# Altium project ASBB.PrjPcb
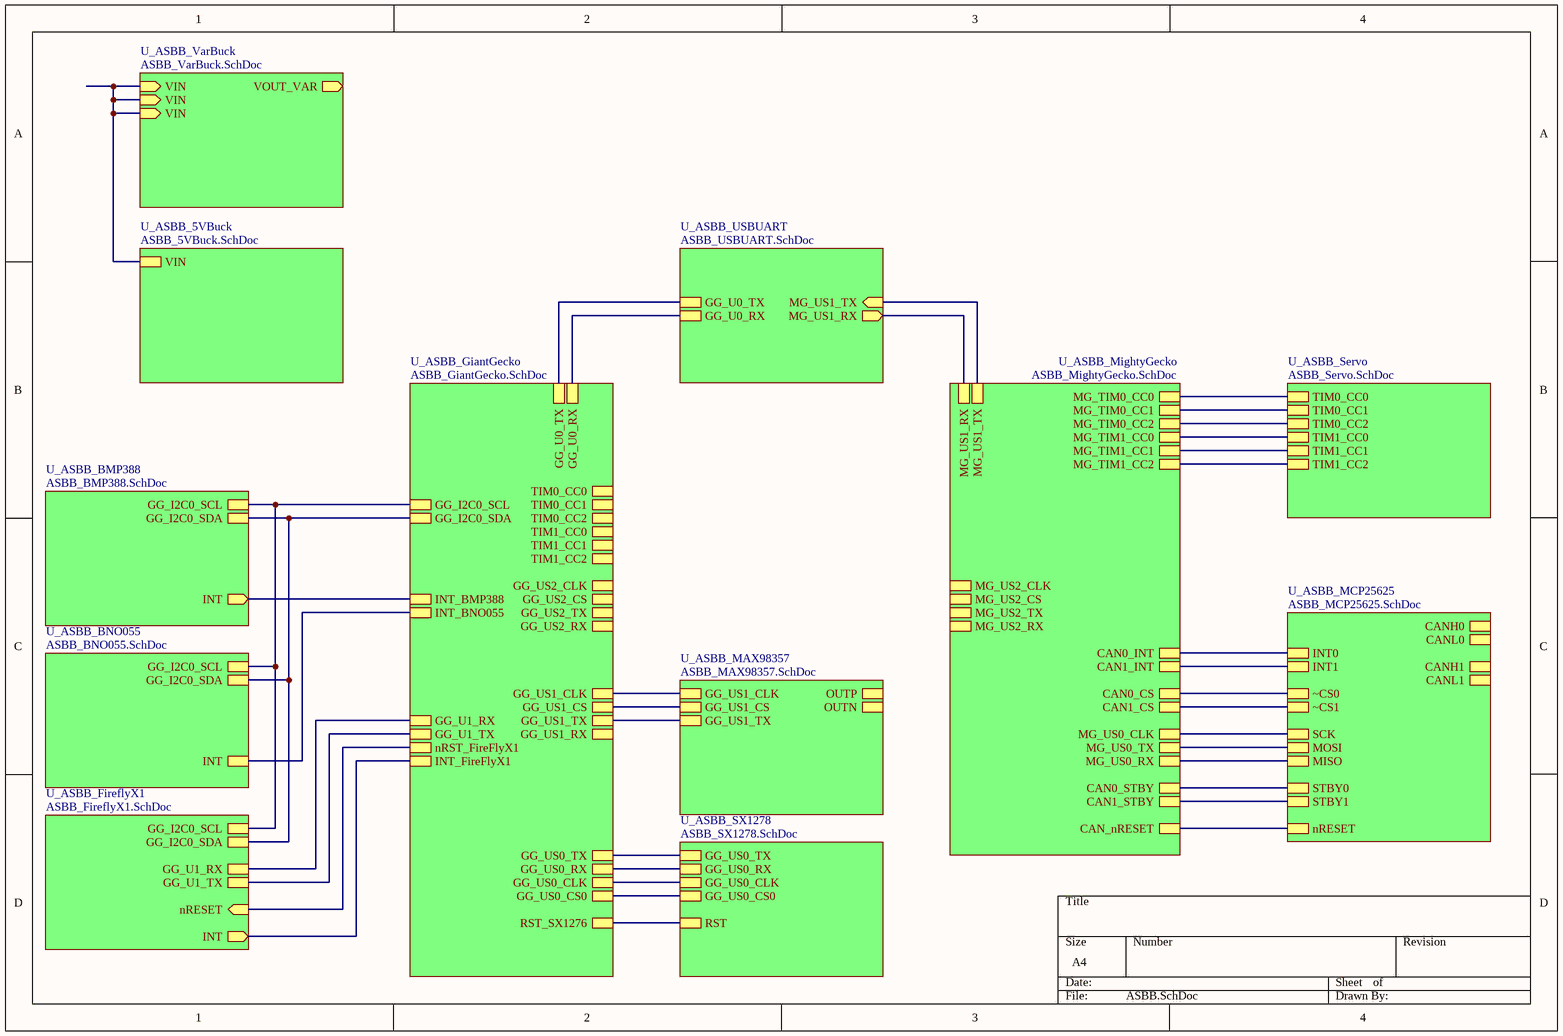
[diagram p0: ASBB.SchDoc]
13 sheets, 166 parts. Net scope: hierarchical (ports join the sheet entries above them; power ports are global).
Sheets:
  ASBB.SchDoc
    U_ASBB_VarBuck = ASBB_VarBuck.SchDoc
    U_ASBB_5VBuck = ASBB_5VBuck.SchDoc
    U_ASBB_USBUART = ASBB_USBUART.SchDoc
    U_ASBB_BMP388 = ASBB_BMP388.SchDoc
    U_ASBB_BNO055 = ASBB_BNO055.SchDoc
    U_ASBB_MAX98357 = ASBB_MAX98357.SchDoc
    U_ASBB_MCP25625 = ASBB_MCP25625.SchDoc
    U_ASBB_FireflyX1 = ASBB_FireflyX1.SchDoc
    U_ASBB_SX1278 = ASBB_SX1278.SchDoc
    U_ASBB_GiantGecko = ASBB_GiantGecko.SchDoc
    U_ASBB_Servo = ASBB_Servo.SchDoc
    U_ASBB_MightyGecko = ASBB_MightyGecko.SchDoc

## Sheet ASBB.SchDoc
size A4

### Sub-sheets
U_ASBB_5VBuck = ASBB_5VBuck.SchDoc: VIN
U_ASBB_BMP388 = ASBB_BMP388.SchDoc: INT (out), GG_I2C0_SCL, GG_I2C0_SDA
U_ASBB_BNO055 = ASBB_BNO055.SchDoc: INT, GG_I2C0_SCL, GG_I2C0_SDA
U_ASBB_FireflyX1 = ASBB_FireflyX1.SchDoc: INT (out), nRESET (in), GG_U1_TX, GG_I2C0_SCL, GG_U1_RX, GG_I2C0_SDA
U_ASBB_GiantGecko = ASBB_GiantGecko.SchDoc: GG_U0_TX, GG_US1_CLK, GG_US0_CS0, GG_US2_RX, GG_U1_RX, GG_US2_CLK, GG_US1_TX, GG_US0_TX, GG_US2_TX, GG_US1_RX, GG_I2C0_SDA, GG_U1_TX, GG_US2_CS, GG_U0_RX, GG_US0_RX, GG_US1_CS, GG_US0_CLK, GG_I2C0_SCL, INT_BNO055, INT_BMP388, nRST_FireFlyX1, INT_FireFlyX1, RST_SX1276, TIM1_CC1, TIM0_CC0, TIM1_CC0, TIM0_CC2, TIM1_CC2, TIM0_CC1
U_ASBB_MAX98357 = ASBB_MAX98357.SchDoc: OUTP, OUTN, GG_US1_CLK, GG_US1_CS, GG_US1_TX
U_ASBB_MCP25625 = ASBB_MCP25625.SchDoc: INT0, INT1, CANH0, CANL0, CANH1, CANL1, ~CS0, SCK, MOSI, MISO, ~CS1, STBY1, STBY0, nRESET
U_ASBB_MightyGecko = ASBB_MightyGecko.SchDoc: MG_US0_CLK, MG_US0_RX, MG_US0_TX, MG_US2_CLK, MG_US2_RX, MG_US2_TX, MG_US2_CS, MG_US1_RX, MG_US1_TX, MG_TIM0_CC0, MG_TIM1_CC0, MG_TIM0_CC1, MG_TIM0_CC2, CAN1_INT, CAN0_STBY, CAN0_CS, CAN_nRESET, CAN1_CS, CAN0_INT, CAN1_STBY, MG_TIM1_CC1, MG_TIM1_CC2
U_ASBB_Servo = ASBB_Servo.SchDoc: TIM0_CC0, TIM0_CC1, TIM0_CC2, TIM1_CC0, TIM1_CC1, TIM1_CC2
U_ASBB_SX1278 = ASBB_SX1278.SchDoc: RST, GG_US0_TX, GG_US0_RX, GG_US0_CLK, GG_US0_CS0
U_ASBB_USBUART = ASBB_USBUART.SchDoc: GG_U0_TX, GG_U0_RX, MG_US1_TX (in), MG_US1_RX (out)
U_ASBB_VarBuck = ASBB_VarBuck.SchDoc: VIN (in), VIN (in), VIN (in), VOUT_VAR (out)

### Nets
GG_US0_CLK: sheet U_ASBB_SX1278/GG_US0_CLK, sheet U_ASBB_GiantGecko/GG_US0_CLK
GG_US0_RX: sheet U_ASBB_SX1278/GG_US0_RX, sheet U_ASBB_GiantGecko/GG_US0_RX
GG_US0_TX: sheet U_ASBB_SX1278/GG_US0_TX, sheet U_ASBB_GiantGecko/GG_US0_TX
V_IN: sheet U_ASBB_VarBuck/VIN, sheet U_ASBB_VarBuck/VIN, sheet U_ASBB_VarBuck/VIN, sheet U_ASBB_5VBuck/VIN
NetB?_10: sheet U_ASBB_BMP388/GG_I2C0_SDA, sheet U_ASBB_BNO055/GG_I2C0_SDA, sheet U_ASBB_FireflyX1/GG_I2C0_SDA, sheet U_ASBB_GiantGecko/GG_I2C0_SDA
NetB?_11: sheet U_ASBB_BMP388/GG_I2C0_SCL, sheet U_ASBB_BNO055/GG_I2C0_SCL, sheet U_ASBB_FireflyX1/GG_I2C0_SCL, sheet U_ASBB_GiantGecko/GG_I2C0_SCL
NetB?_13: sheet U_ASBB_FireflyX1/INT, sheet U_ASBB_GiantGecko/INT_FireFlyX1
NetB?_19: sheet U_ASBB_FireflyX1/nRESET, sheet U_ASBB_GiantGecko/nRST_FireFlyX1
NetIC?#3_2: sheet U_ASBB_SX1278/GG_US0_CS0, sheet U_ASBB_GiantGecko/GG_US0_CS0
NetIC?#3_4: sheet U_ASBB_SX1278/RST, sheet U_ASBB_GiantGecko/RST_SX1276
NetIC?#4_4: sheet U_ASBB_MCP25625/STBY1, sheet U_ASBB_MightyGecko/CAN1_STBY
NetIC?#4_19: sheet U_ASBB_MCP25625/MOSI, sheet U_ASBB_MightyGecko/MG_US0_TX
NetIC?#4_20: sheet U_ASBB_MCP25625/MISO, sheet U_ASBB_MightyGecko/MG_US0_RX
NetIC?#4_21: sheet U_ASBB_MCP25625/SCK, sheet U_ASBB_MightyGecko/MG_US0_CLK
NetIC?#4_30: sheet U_ASBB_Servo/TIM1_CC2, sheet U_ASBB_MightyGecko/MG_TIM1_CC2
NetIC?#4_31: sheet U_ASBB_Servo/TIM1_CC1, sheet U_ASBB_MightyGecko/MG_TIM1_CC1
NetIC?#4_32: sheet U_ASBB_MCP25625/nRESET, sheet U_ASBB_MightyGecko/CAN_nRESET
NetIC?#4_33: sheet U_ASBB_USBUART/MG_US1_RX, sheet U_ASBB_MightyGecko/MG_US1_RX
NetIC?#4_34: sheet U_ASBB_USBUART/MG_US1_TX, sheet U_ASBB_MightyGecko/MG_US1_TX
NetIC?#4_45: sheet U_ASBB_Servo/TIM0_CC0, sheet U_ASBB_MightyGecko/MG_TIM0_CC0
NetIC?#4_47: sheet U_ASBB_Servo/TIM0_CC1, sheet U_ASBB_MightyGecko/MG_TIM0_CC1
NetIC?#4_49: sheet U_ASBB_Servo/TIM0_CC2, sheet U_ASBB_MightyGecko/MG_TIM0_CC2
NetIC?#4_50: sheet U_ASBB_MCP25625/STBY0, sheet U_ASBB_MightyGecko/CAN0_STBY
NetIC?#4_51: sheet U_ASBB_Servo/TIM1_CC0, sheet U_ASBB_MightyGecko/MG_TIM1_CC0
NetIC?#4_52: sheet U_ASBB_MCP25625/INT0, sheet U_ASBB_MightyGecko/CAN0_INT
NetIC?#4_54: sheet U_ASBB_MCP25625/INT1, sheet U_ASBB_MightyGecko/CAN1_INT
NetIC?#4_57: sheet U_ASBB_MCP25625/~CS0, sheet U_ASBB_MightyGecko/CAN0_CS
NetIC?#4_58: sheet U_ASBB_MCP25625/~CS1, sheet U_ASBB_MightyGecko/CAN1_CS
NetR?#28_2: sheet U_ASBB_FireflyX1/GG_U1_TX, sheet U_ASBB_GiantGecko/GG_U1_TX
NetR?#29_2: sheet U_ASBB_FireflyX1/GG_U1_RX, sheet U_ASBB_GiantGecko/GG_U1_RX
NetU?#2_2: sheet U_ASBB_USBUART/GG_U0_TX, sheet U_ASBB_GiantGecko/GG_U0_TX
NetU?#2_30: sheet U_ASBB_USBUART/GG_U0_RX, sheet U_ASBB_GiantGecko/GG_U0_RX
NetU?#3_7: sheet U_ASBB_BMP388/INT, sheet U_ASBB_GiantGecko/INT_BMP388
NetU?#4_14: sheet U_ASBB_BNO055/INT, sheet U_ASBB_GiantGecko/INT_BNO055
NetU?#5_1: sheet U_ASBB_MAX98357/GG_US1_TX, sheet U_ASBB_GiantGecko/GG_US1_TX
NetU?#5_14: sheet U_ASBB_MAX98357/GG_US1_CS, sheet U_ASBB_GiantGecko/GG_US1_CS
NetU?#5_16: sheet U_ASBB_MAX98357/GG_US1_CLK, sheet U_ASBB_GiantGecko/GG_US1_CLK

## Sheet ASBB_VarBuck.SchDoc
size A4
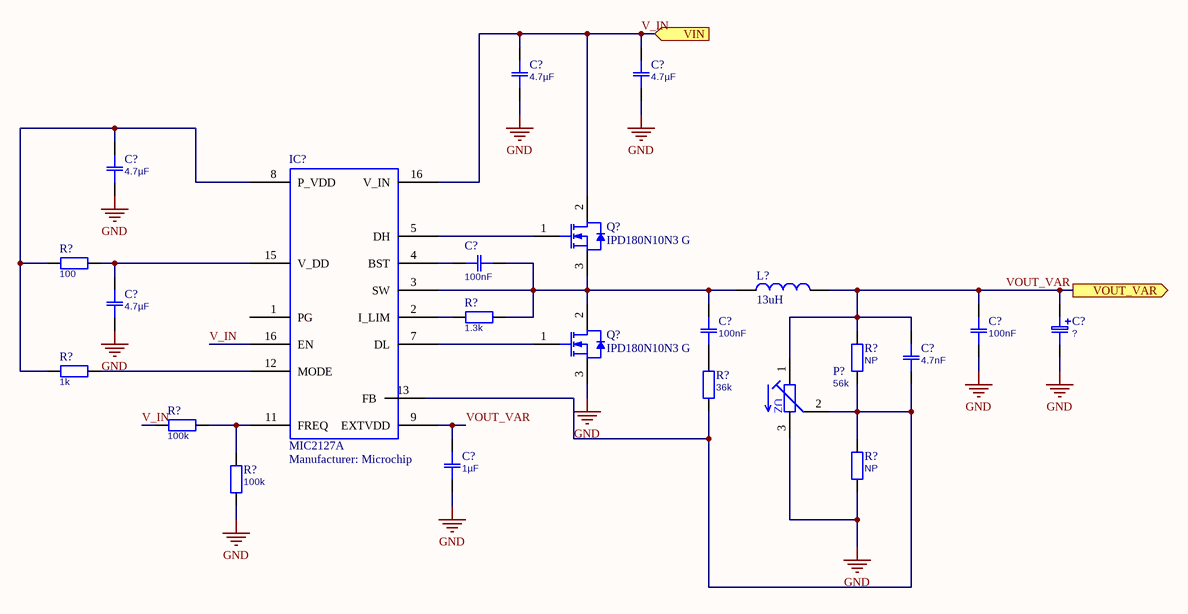
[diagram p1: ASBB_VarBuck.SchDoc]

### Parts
(Parts that share a designator on the sheet are numbered #1, #2 ... from top to bottom, then left to right.)
C?#1  4.7µF  [0603]
C?#2  4.7µF  [0603]
C?#3  4.7µF  [0603]
C?#4  100nF  [0603]
C?#5  4.7µF  [0603]
C?#6  100nF  [0603]
C?#7  100nF  [0603]
C?#8  ?  [SMELK-A]
C?#9  4.7nF  [0603]
C?#10  1µF  [0603]
IC?#1  MIC2127A  Manufacturer: Microchip  [QFN-MG16_M]
L?#1  value 13uH  [WE-HCI_1365_WE-PERM]  (hidden comment: 7443551131)
P?#1  56k  [Model 43 Trimmer]
Q?#1  IPD180N10N3 G  [INF-PG-TO252-3-11_A_N]
Q?#2  IPD180N10N3 G  [INF-PG-TO252-3-11_A_N]
R?#1  100  [0603]
R?#2  1.3k  [0603]
R?#3  1k  [0603]
R?#4  NP  [0603]
R?#5  36k  [0603]
R?#6  100k  [0603]
R?#7  NP  [0603]
R?#8  100k  [0603]

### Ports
VIN (in), VOUT_VAR (out)

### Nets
GND: C?#1.1 C?#2.1 C?#3.2 C?#5.2 C?#7.2 C?#8.2(-) C?#10.2 P?#1.3 Q?#2.3(SOURCE) R?#7.1 R?#8.1
V_IN: C?#1.2 C?#2.2 IC?#1.16(EN) Q?#1.2(DRAIN) R?#6.1 ; port VIN
VOUT_VAR: C?#7.1 C?#8.1(+) C?#9.1 C?#10.1 IC?#1.9(EXTVDD) L?#1.2 P?#1.1 R?#4.2 ; port VOUT_VAR
NetC?#3_1: C?#3.1 IC?#1.8(P_VDD) R?#1.1 R?#3.1
NetC?#4_1: C?#4.1 C?#6.1 IC?#1.3(SW) L?#1.1 Q?#1.3(SOURCE) Q?#2.2(DRAIN) R?#2.2
NetC?#4_2: C?#4.2 IC?#1.4(BST)
NetC?#5_1: C?#5.1 IC?#1.15(V_DD) R?#1.2
NetC?#6_2: C?#6.2 R?#5.2
NetC?#9_2: C?#9.2 IC?#1.13(FB) P?#1.2 R?#4.1 R?#5.1 R?#7.2
NetIC?#1_2: IC?#1.2(I_LIM) R?#2.1
NetIC?#1_5: IC?#1.5(DH) Q?#1.1(GATE)
NetIC?#1_7: IC?#1.7(DL) Q?#2.1(GATE)
NetIC?#1_11: IC?#1.11(FREQ) R?#6.2 R?#8.2
NetIC?#1_12: IC?#1.12(MODE) R?#3.2

Not connected (* = marked no-connect by the designer): IC?#1 1(PG)

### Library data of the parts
C?#1-C?#7 C?#9 C?#10 = Capacitor
C?#8 = Capacitor polarised: Capacitor, polarised
IC?#1 = MIC2127A: 75V, Synchronous Buck Controller Featuring ADaptive On-Time Control
L?#1 = 7443551131: WE-HCI SMD Flat Wire High Current Inductor, size 1365, 10A, 13uH; Material: WE-PERM
P?#1 = Potentiometer
Q?#1 Q?#2 = IPD180N10N3 G: N-Channel OptiMOS 3 Power-Transistor, 100 V VDS, 43 A ID, -55 to 175 degC, PG-TO252-3-11, Reel, Green; Manufacturer: Infineon; Green: TRUE; ID (max): 43 A; IDpuls (max): 172 A; Polarity: N; Ptot (max): 71 W; QG: 19 nC; RDS (on) (max): 18 mOhm; Rth: 2.1 K/W; RthJA (max): 75 K/W; VDS (max): 100 V; VGS(th) (max): 3.5 V; VGS(th) (min): 2 V
R?#1-R?#8 = Resistor

## Sheet ASBB_5VBuck.SchDoc
size A4
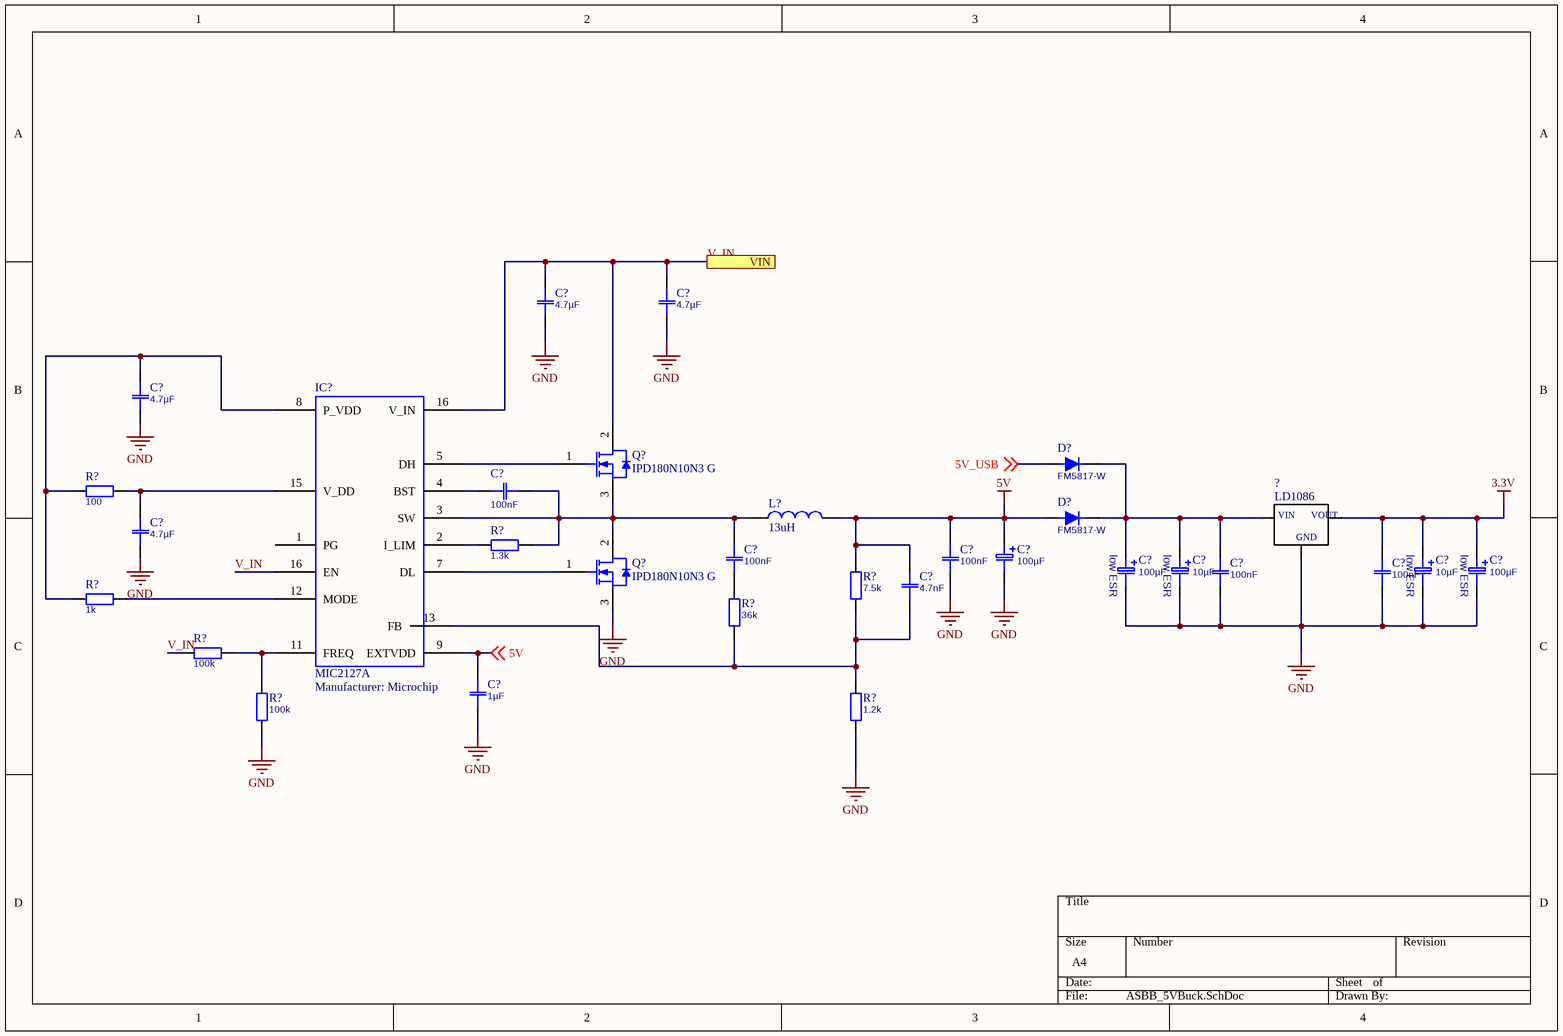
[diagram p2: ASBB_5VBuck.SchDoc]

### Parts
(Parts that share a designator on the sheet are numbered #1, #2 ... from top to bottom, then left to right.)
?  LD1086  [D2PAK_LD1086(Primary)]
C?#11  4.7µF  [0603]
C?#12  4.7µF  [0603]
C?#13  4.7µF  [0603]
C?#14  100nF  [0603]
C?#15  4.7µF  [0603]
C?#16  100nF  [0603]
C?#17  100nF  [0603]
C?#18  100µF  [SMELK-A]
C?#19  100µF  [SMELK-C]
C?#20  10µF  [SMELK-C]
C?#21  10µF  [SMELK-C]
C?#22  100µF  [SMELK-C]
C?#23  4.7nF  [0603]
C?#24  100nF  [0603]
C?#25  100nF  [0603]
C?#26  1µF  [0603]
D?#1  FM5817-W  [SMB]
D?#2  FM5817-W  [SMB]
IC?#2  MIC2127A  Manufacturer: Microchip  [QFN-MG16_M]
L?#2  value 13uH  [WE-HCI_1365_WE-PERM]  (hidden comment: 7443551131)
Q?#3  IPD180N10N3 G  [INF-PG-TO252-3-11_A_N]
Q?#4  IPD180N10N3 G  [INF-PG-TO252-3-11_A_N]
R?#9  100  [0603]
R?#10  1.3k  [0603]
R?#11  1k  [0603]
R?#12  7.5k  [0603]
R?#13  36k  [0603]
R?#14  100k  [0603]
R?#15  100k  [0603]
R?#16  1.2k  [0603]

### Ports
VIN

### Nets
3.3V: ?.VOUT C?#21.1(+) C?#22.1(+) C?#25.2
5V: C?#17.1 C?#18.1(+) C?#23.1 C?#26.1 D?#2.2(A) IC?#2.9(EXTVDD) L?#2.2 R?#12.2 ; off-sheet 5V
GND: ?.GND C?#11.1 C?#12.1 C?#13.2 C?#15.2 C?#17.2 C?#18.2(-) C?#19.2(-) C?#20.2(-) C?#21.2(-) C?#22.2(-) C?#24.1 C?#25.1 C?#26.2 Q?#4.3(SOURCE) R?#15.1 R?#16.1
5V_USB: D?#1.2(A) ; off-sheet 5V_USB
V_IN: C?#11.2 C?#12.2 IC?#2.16(EN) Q?#3.2(DRAIN) R?#14.1 ; port VIN
Net?_VIN: ?.VIN C?#19.1(+) C?#20.1(+) C?#24.2 D?#1.1(C) D?#2.1(C)
NetC?#13_1: C?#13.1 IC?#2.8(P_VDD) R?#9.1 R?#11.1
NetC?#14_1: C?#14.1 C?#16.1 IC?#2.3(SW) L?#2.1 Q?#3.3(SOURCE) Q?#4.2(DRAIN) R?#10.2
NetC?#14_2: C?#14.2 IC?#2.4(BST)
NetC?#15_1: C?#15.1 IC?#2.15(V_DD) R?#9.2
NetC?#16_2: C?#16.2 R?#13.2
NetC?#23_2: C?#23.2 IC?#2.13(FB) R?#12.1 R?#13.1 R?#16.2
NetIC?#2_2: IC?#2.2(I_LIM) R?#10.1
NetIC?#2_5: IC?#2.5(DH) Q?#3.1(GATE)
NetIC?#2_7: IC?#2.7(DL) Q?#4.1(GATE)
NetIC?#2_11: IC?#2.11(FREQ) R?#14.2 R?#15.2
NetIC?#2_12: IC?#2.12(MODE) R?#11.2

Not connected (* = marked no-connect by the designer): IC?#2 1(PG)

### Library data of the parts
? = LD1086: Semiconductors and Actives; MF: STMicroelectronics
C?#11-C?#17 C?#23-C?#26 = Capacitor
C?#18 = Capacitor polarised: Capacitor, polarised
C?#19-C?#22 = Capacitor polarised low ESR: Capacitor, polarised, low ESR
D?#1 D?#2 = Diode
IC?#2 = MIC2127A: as IC?#1 on sheet ASBB_VarBuck
L?#2 = 7443551131: as L?#1 on sheet ASBB_VarBuck
Q?#3 Q?#4 = IPD180N10N3 G: as Q?#1 on sheet ASBB_VarBuck
R?#9-R?#16 = Resistor

## Sheet ASBB_USBUART.SchDoc
size A4
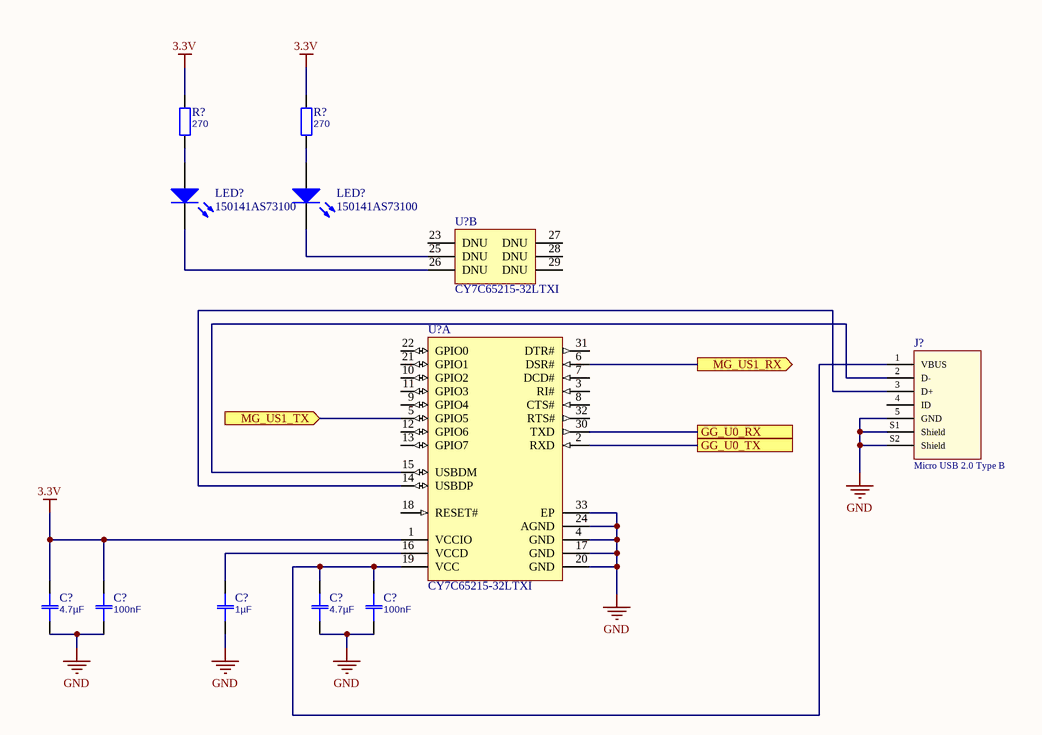
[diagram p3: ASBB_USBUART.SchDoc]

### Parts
(Parts that share a designator on the sheet are numbered #1, #2 ... from top to bottom, then left to right.)
C?#27  4.7µF  [0603]
C?#28  100nF  [0603]
C?#29  1µF  [0603]
C?#30  4.7µF  [0603]
C?#31  100nF  [0603]
J?#1  Micro USB 2.0 Type B  [614105150721]
LED?#1  150141AS73100  [3528]
LED?#2  150141AS73100  [3528]
R?#17  270  [0603]
R?#18  270  [0603]
U?#1  CY7C65215-32LTXI  [CYP-LTX32_N]  (part B of 2)
U?#2  CY7C65215-32LTXI  [CYP-LTX32_N]  (part A of 2)

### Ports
GG_U0_RX, GG_U0_TX, MG_US1_RX (out), MG_US1_TX (in)

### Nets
3.3V: C?#27.2 C?#28.2 R?#17.2 R?#18.2 U?#2.1(VCCIO)
GND: C?#27.1 C?#28.1 C?#29.1 C?#30.1 C?#31.1 J?#1.5(GND) J?#1.S1(Shield) J?#1.S2(Shield) U?#2.4(GND) U?#2.17(GND) U?#2.20(GND) U?#2.24(AGND) U?#2.33(EP)
NetC?#29_2: C?#29.2 U?#2.16(VCCD)
NetC?#30_2: C?#30.2 C?#31.2 J?#1.1(VBUS) U?#2.19(VCC)
NetIC?#4_33: U?#2.6(DSR#) ; port MG_US1_RX
NetIC?#4_34: U?#2.5(GPIO5) ; port MG_US1_TX
NetJ?#1_2: J?#1.2(D-) U?#2.15(USBDM)
NetJ?#1_3: J?#1.3(D+) U?#2.14(USBDP)
NetLED?#1_1: LED?#1.1(K) U?#1.26(DNU)
NetLED?#1_2: LED?#1.2(A) R?#17.1
NetLED?#2_1: LED?#2.1(K) U?#1.25(DNU)
NetLED?#2_2: LED?#2.2(A) R?#18.1
NetU?#2_2: U?#2.2(RXD) ; port GG_U0_TX
NetU?#2_30: U?#2.30(TXD) ; port GG_U0_RX

Not connected (* = marked no-connect by the designer): J?#1 4(ID); U?#1 23(DNU) 27(DNU) 28(DNU) 29(DNU); U?#2 3(RI#) 7(DCD#) 8(CTS#) 9(GPIO4) 10(GPIO2) 11(GPIO3) 12(GPIO6) 13(GPIO7) 18(RESET#) 21(GPIO1) 22(GPIO0) 31(DTR#) 32(RTS#)

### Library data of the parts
C?#27-C?#31 = Capacitor
J?#1 = 614105150721: Micro USB 2.0 Type B Vertical THT 5 Contacts WR-COM; Rated Current: 1 A; Gender: Female
LED?#1 LED?#2 = 150141AS73100: SMD mono-color Top LED, WL-SMTW, Amber
R?#17 R?#18 = Resistor
U?#1 U?#2 = CY7C65215-32LTXI: USB-Serial Dual Channel (UART/I2C/SPI) Bridge with CapSense(R) and BCD, 0.5 KB, 19 I/Os, 1.71 to 5.5 V, -40 to 85 degC, 32-Pin QFN (LTX32), Tray; Manufacturer: Cypress; CPU Core: M8; Max. Operating Voltage (V): 5.5; Memory Architecture: Flash; Memory Size (KB): 0.5; Min. Operating Voltage (V): 1.71; No. of I/Os: 19

## Sheet ASBB_BMP388.SchDoc
size A4
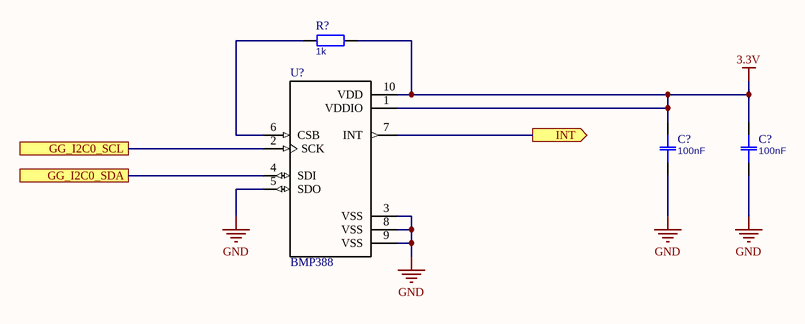
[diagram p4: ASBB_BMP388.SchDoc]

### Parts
(Parts that share a designator on the sheet are numbered #1, #2 ... from top to bottom, then left to right.)
C?#32  100nF  [0603]
C?#33  100nF  [0603]
R?#19  1k  [0603]
U?#3  BMP388  [PQFN50P200X200X80-10N]

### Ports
GG_I2C0_SCL, GG_I2C0_SDA, INT (out)

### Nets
3.3V: C?#32.2 C?#33.2 R?#19.2 U?#3.1(VDDIO) U?#3.10(VDD)
GND: C?#32.1 C?#33.1 U?#3.3(VSS) U?#3.5(SDO) U?#3.8(VSS) U?#3.9(VSS)
NetB?_10: U?#3.4(SDI) ; port GG_I2C0_SDA
NetB?_11: U?#3.2(SCK) ; port GG_I2C0_SCL
NetR?#19_1: R?#19.1 U?#3.6(CSB)
NetU?#3_7: U?#3.7(INT) ; port INT

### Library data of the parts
C?#32 C?#33 = Capacitor
R?#19 = Resistor
U?#3 = BMP388: P-Sensor SPI I2C 1, 25 Bar SMD; MF: Bosch Sensortec

## Sheet ASBB_BNO055.SchDoc
size A4
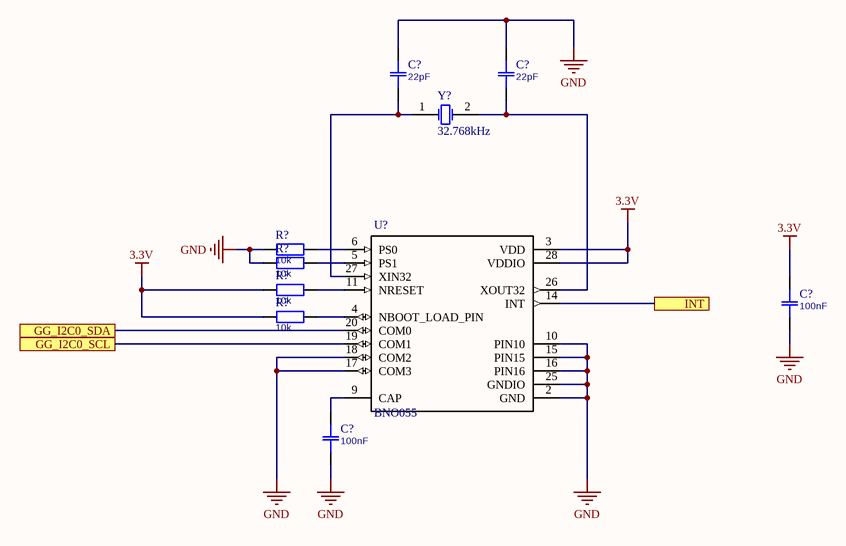
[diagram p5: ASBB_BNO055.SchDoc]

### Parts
(Parts that share a designator on the sheet are numbered #1, #2 ... from top to bottom, then left to right.)
C?#34  22pF  [0603]
C?#35  22pF  [0603]
C?#36  100nF  [0603]
C?#37  100nF  [0603]
R?#20  10k  [0603]
R?#21  10k  [0603]
R?#22  10k  [0603]
R?#23  10k  [0603]
U?#4  BNO055  [LGA28R50P4X10_380X520X100]
Y?#1  32.768kHz  [R38]

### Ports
GG_I2C0_SCL, GG_I2C0_SDA, INT

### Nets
3.3V: C?#36.2 R?#22.1 R?#23.1 U?#4.3(VDD) U?#4.28(VDDIO)
GND: C?#34.2 C?#35.2 C?#36.1 C?#37.1 R?#20.1 R?#21.1 U?#4.2(GND) U?#4.10(PIN10) U?#4.15(PIN15) U?#4.16(PIN16) U?#4.17(COM3) U?#4.18(COM2) U?#4.25(GNDIO)
NetB?_10: U?#4.20(COM0) ; port GG_I2C0_SDA
NetB?_11: U?#4.19(COM1) ; port GG_I2C0_SCL
NetC?#34_1: C?#34.1 U?#4.27(XIN32) Y?#1.1(OSC1)
NetC?#35_1: C?#35.1 U?#4.26(XOUT32) Y?#1.2(OSC2)
NetC?#37_2: C?#37.2 U?#4.9(CAP)
NetR?#20_2: R?#20.2 U?#4.6(PS0)
NetR?#21_2: R?#21.2 U?#4.5(PS1)
NetR?#22_2: R?#22.2 U?#4.11(NRESET)
NetR?#23_2: R?#23.2 U?#4.4(NBOOT_LOAD_PIN)
NetU?#4_14: U?#4.14(INT) ; port INT

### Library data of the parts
C?#34-C?#37 = Capacitor
R?#20-R?#23 = Resistor
U?#4 = BNO055: BNO055 9-axis Absolute Orientation Sensor _ SiP _ w/Sensors and Sensor Fusion; MF: Bosch
Y?#1 = XTAL: Crystal Oscillator

## Sheet ASBB_MAX98357.SchDoc
size A4
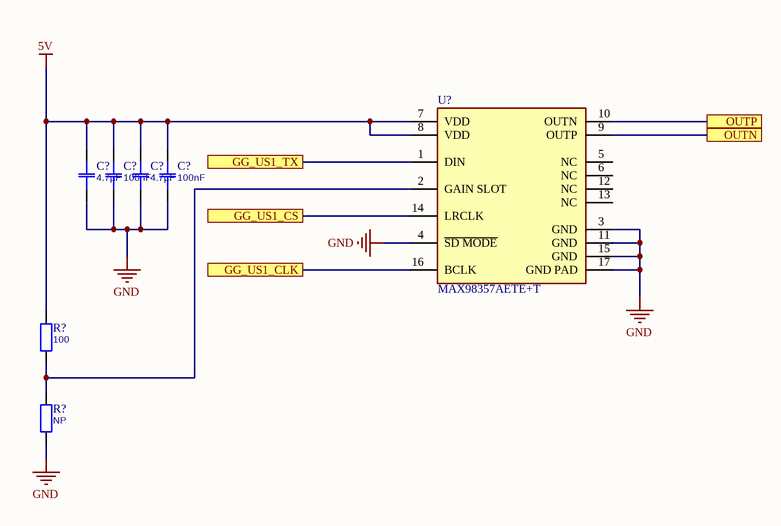
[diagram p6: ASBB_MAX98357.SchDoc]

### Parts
(Parts that share a designator on the sheet are numbered #1, #2 ... from top to bottom, then left to right.)
C?#38  4.7µF  [0603]
C?#39  100nF  [0603]
C?#40  4.7µF  [0603]
C?#41  100nF  [0603]
R?#24  100  [0603]
R?#25  NP  [0603]
U?#5  Part Number: MAX98357AETE+T  [Maxim_Electronics_21-0896_0]  (hidden comment: IC_Maxim_Electronics_MAX98357AETE+T_eec)

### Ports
GG_US1_CLK, GG_US1_CS, GG_US1_TX, OUTN, OUTP

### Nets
5V: C?#38.2 C?#39.2 C?#40.2 C?#41.2 R?#24.2 U?#5.7(VDD) U?#5.8(VDD)
GND: C?#38.1 C?#39.1 C?#40.1 C?#41.1 R?#25.1 U?#5.3(GND) U?#5.4(~{SD_MODE}) U?#5.11(GND) U?#5.15(GND) U?#5.17(GND_PAD)
NetR?#24_1: R?#24.1 R?#25.2 U?#5.2(GAIN_SLOT)
NetU?#5_1: U?#5.1(DIN) ; port GG_US1_TX
NetU?#5_9: U?#5.9(OUTP) ; port OUTN
NetU?#5_10: U?#5.10(OUTN) ; port OUTP
NetU?#5_14: U?#5.14(LRCLK) ; port GG_US1_CS
NetU?#5_16: U?#5.16(BCLK) ; port GG_US1_CLK

Not connected (* = marked no-connect by the designer): U?#5 5(NC) 6(NC) 12(NC) 13(NC)

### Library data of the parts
C?#38-C?#41 = Capacitor
R?#24 R?#25 = Resistor
U?#5 = IC_Maxim_Electronics_MAX98357AETE+T_eec: IC Amplifier IC 2-Channel (Stereo) Class D 16-TQFN (3x3); Manufacturer: Maxim Electronics; Mfg Package Ident: 21-0896

## Sheet ASBB_MCP25625.SchDoc
size A4
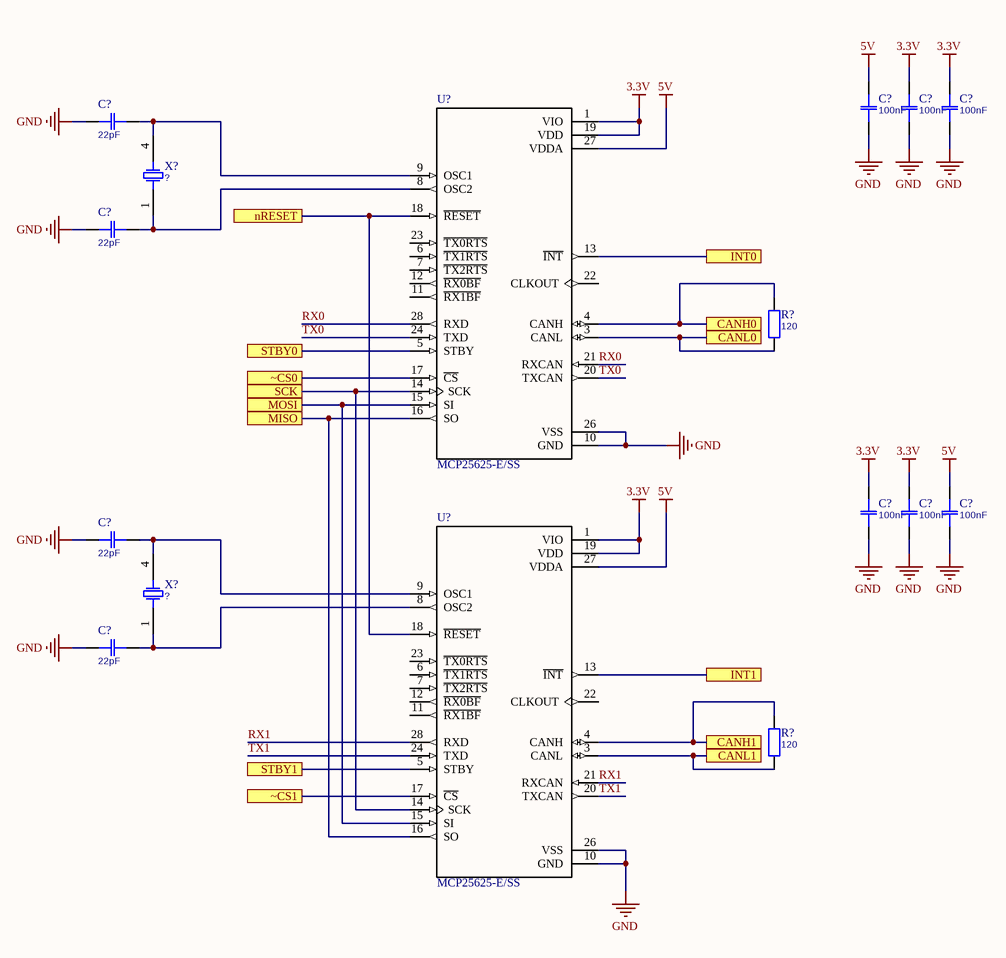
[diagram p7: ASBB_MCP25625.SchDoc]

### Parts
(Parts that share a designator on the sheet are numbered #1, #2 ... from top to bottom, then left to right.)
C?#42  100nF  [0603]
C?#43  22pF  [0603]
C?#44  100nF  [0603]
C?#45  100nF  [0603]
C?#46  22pF  [0603]
C?#47  22pF  [0603]
C?#48  100nF  [0603]
C?#49  100nF  [0603]
C?#50  100nF  [0603]
C?#51  22pF  [0603]
R?#26  120  [0603]
R?#27  120  [0603]
U?#6  MCP25625-E/SS  [SOP65P780X200-28N]
U?#7  MCP25625-E/SS  [SOP65P780X200-28N]
X?#1  ?  [MA-506]
X?#2  ?  [MA-506]

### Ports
CANH0, CANH1, CANL0, CANL1, INT0, INT1, MISO, MOSI, nRESET, SCK, STBY0, STBY1, ~CS0, ~CS1

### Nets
3.3V: C?#44.2 C?#45.2 C?#48.2 C?#49.2 U?#6.1(VIO) U?#6.19(VDD) U?#7.1(VIO) U?#7.19(VDD)
5V: C?#42.1 C?#50.2 U?#6.27(VDDA) U?#7.27(VDDA)
GND: C?#42.2 C?#43.2 C?#44.1 C?#45.1 C?#46.2 C?#47.2 C?#48.1 C?#49.1 C?#50.1 C?#51.2 U?#6.10(GND) U?#6.26(VSS) U?#7.10(GND) U?#7.26(VSS)
RX0: U?#6.21(RXCAN) U?#6.28(RXD)
RX1: U?#7.21(RXCAN) U?#7.28(RXD)
TX0: U?#6.20(TXCAN) U?#6.24(TXD)
TX1: U?#7.20(TXCAN) U?#7.24(TXD)
NetC?#43_1: C?#43.1 U?#6.9(OSC1) X?#1.4
NetC?#46_1: C?#46.1 U?#6.8(OSC2) X?#1.1
NetC?#47_1: C?#47.1 U?#7.9(OSC1) X?#2.4
NetC?#51_1: C?#51.1 U?#7.8(OSC2) X?#2.1
NetIC?#4_4: U?#7.5(STBY) ; port STBY1
NetIC?#4_19: U?#6.15(SI) U?#7.15(SI) ; port MOSI
NetIC?#4_20: U?#6.16(SO) U?#7.16(SO) ; port MISO
NetIC?#4_21: U?#6.14(SCK) U?#7.14(SCK) ; port SCK
NetIC?#4_32: U?#6.18(~{RESET}) U?#7.18(~{RESET}) ; port nRESET
NetIC?#4_50: U?#6.5(STBY) ; port STBY0
NetIC?#4_52: U?#6.13(~{INT}) ; port INT0
NetIC?#4_54: U?#7.13(~{INT}) ; port INT1
NetIC?#4_57: U?#6.17(~{CS}) ; port ~CS0
NetIC?#4_58: U?#7.17(~{CS}) ; port ~CS1
NetR?#26_1: R?#26.1 U?#6.3(CANL) ; port CANL0
NetR?#26_2: R?#26.2 U?#6.4(CANH) ; port CANH0
NetR?#27_1: R?#27.1 U?#7.3(CANL) ; port CANL1
NetR?#27_2: R?#27.2 U?#7.4(CANH) ; port CANH1

Not connected (* = marked no-connect by the designer): U?#6 6(~{TX1RTS}) 7(~{TX2RTS}) 11(~{RX1BF}) 12(~{RX0BF}) 22(CLKOUT) 23(~{TX0RTS}); U?#7 6(~{TX1RTS}) 7(~{TX2RTS}) 11(~{RX1BF}) 12(~{RX0BF}) 22(CLKOUT) 23(~{TX0RTS})

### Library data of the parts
C?#42-C?#51 = Capacitor
R?#26 R?#27 = Resistor
U?#6 U?#7 = MCP25625-E/SS: 28 SSOP .209in TUBECAN Controller with Integrated Transceiver; MF: Microchip
X?#1 X?#2 = Crystal 1-4: Crystal (Pins 1 and 4)

## Sheet ASBB_FireflyX1.SchDoc
size A4
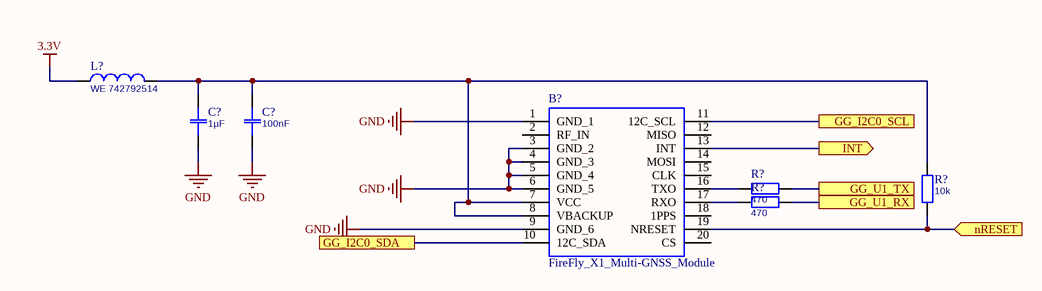
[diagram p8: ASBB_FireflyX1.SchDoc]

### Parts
(Parts that share a designator on the sheet are numbered #1, #2 ... from top to bottom, then left to right.)
B?  FireFly_X1_Multi-GNSS_Module  [X-1]
C?#52  1µF  [0603]
C?#53  100nF  [0603]
L?#3  WE 742792514  [1812]
R?#28  470  [0603]
R?#29  470  [0603]
R?#30  10k  [0603]

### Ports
GG_I2C0_SCL, GG_I2C0_SDA, GG_U1_RX, GG_U1_TX, INT (out), nRESET (in)

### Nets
3.3V: L?#3.1
GND: B?.1(GND_1) B?.3(GND_2) B?.4(GND_3) B?.5(GND_4) B?.6(GND_5) B?.9(GND_6) C?#52.1 C?#53.1
NetB?_7: B?.7(VCC) B?.8(VBACKUP) C?#52.2 C?#53.2 L?#3.2 R?#30.2
NetB?_10: B?.10(12C_SDA) ; port GG_I2C0_SDA
NetB?_11: B?.11(12C_SCL) ; port GG_I2C0_SCL
NetB?_13: B?.13(INT) ; port INT
NetB?_16: B?.16(TXO) R?#28.1
NetB?_17: B?.17(RXO) R?#29.1
NetB?_19: B?.19(NRESET) R?#30.1 ; port nRESET
NetR?#28_2: R?#28.2 ; port GG_U1_TX
NetR?#29_2: R?#29.2 ; port GG_U1_RX

Not connected (* = marked no-connect by the designer): B? 2(RF_IN) 12(MISO) 14(MOSI) 15(CLK) 18(1PPS) 20(CS)

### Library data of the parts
B? = FireFly_X1_Multi-GNSS_Module: Dual system GNSS receiver Module, QFN-20; Manufacturer_Name: GlobalTop Technology Inc.; Manufacturer_Part_Number: FireFly X1 Multi-GNSS Module
C?#52 C?#53 = Capacitor
L?#3 = Inductor
R?#28-R?#30 = Resistor

## Sheet ASBB_SX1278.SchDoc
size A4
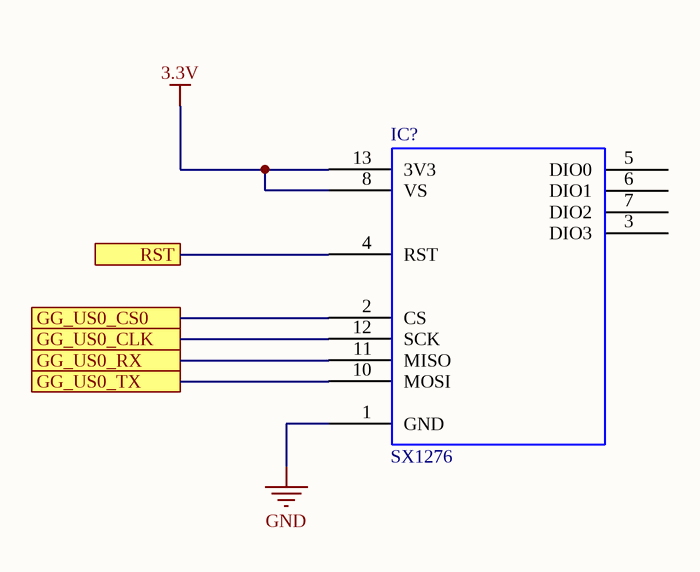
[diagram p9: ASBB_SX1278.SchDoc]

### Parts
(Parts that share a designator on the sheet are numbered #1, #2 ... from top to bottom, then left to right.)
IC?#3  SX1276  [Modtronix inAir9]

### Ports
GG_US0_CLK, GG_US0_CS0, GG_US0_RX, GG_US0_TX, RST

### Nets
3.3V: IC?#3.8(VS) IC?#3.13(3V3)
GND: IC?#3.1(GND)
GG_US0_CLK: IC?#3.12(SCK) ; port GG_US0_CLK
GG_US0_RX: IC?#3.11(MISO) ; port GG_US0_RX
GG_US0_TX: IC?#3.10(MOSI) ; port GG_US0_TX
NetIC?#3_2: IC?#3.2(CS) ; port GG_US0_CS0
NetIC?#3_4: IC?#3.4(RST) ; port RST

Not connected (* = marked no-connect by the designer): IC?#3 3(DIO3) 5(DIO0) 6(DIO1) 7(DIO2) 9(NC) 14(NC)

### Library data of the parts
IC?#3 = Modtronix inAir9: Modtronix LoRa Transceiver

## Sheet ASBB_GiantGecko.SchDoc
size A4
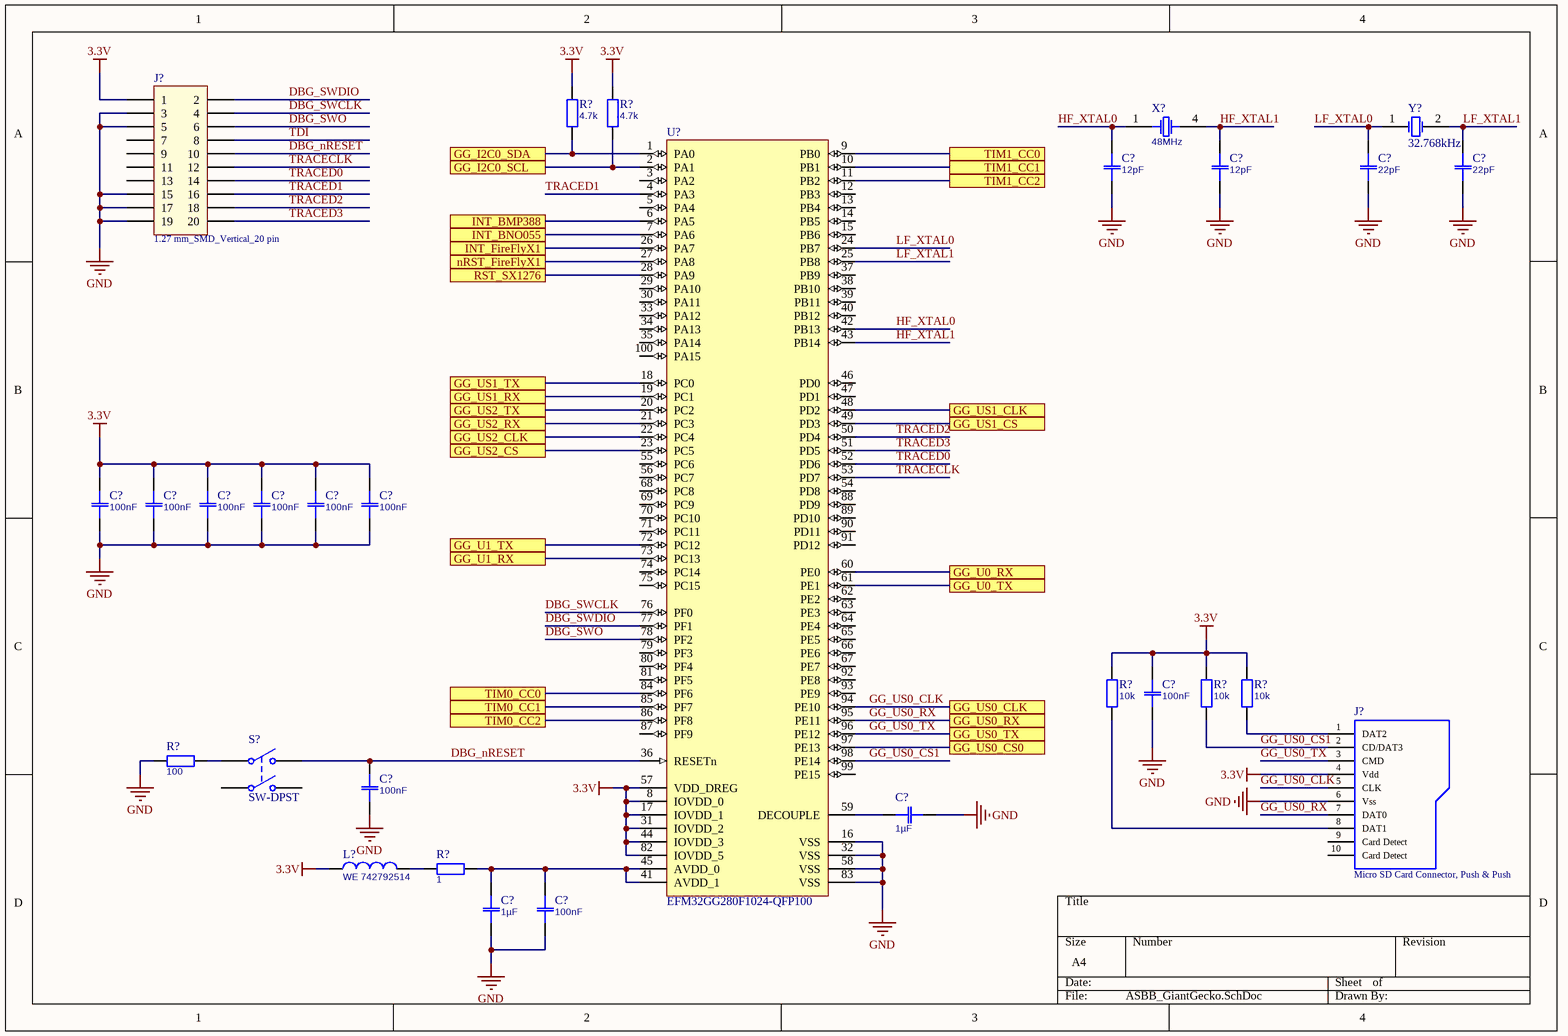
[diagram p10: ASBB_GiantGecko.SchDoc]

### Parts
(Parts that share a designator on the sheet are numbered #1, #2 ... from top to bottom, then left to right.)
C?#54  12pF  [0603]
C?#55  12pF  [0603]
C?#56  22pF  [0603]
C?#57  22pF  [0603]
C?#58  100nF  [0603]
C?#59  100nF  [0603]
C?#60  100nF  [0603]
C?#61  100nF  [0603]
C?#62  100nF  [0603]
C?#63  100nF  [0603]
C?#64  100nF  [0603]
C?#65  100nF  [0603]
C?#66  1µF  [0603]
C?#67  1µF  [0603]
C?#68  100nF  [0603]
J?#2  1.27 mm_SMD_Vertical_20 pin  [62102021021]
J?#3  Micro SD Card Connector, Push & Push  [693071010811]
L?#4  WE 742792514  [1812]
R?#31  4.7k  [0603]
R?#32  4.7k  [0603]
R?#33  10k  [0603]
R?#34  10k  [0603]
R?#35  10k  [0603]
R?#36  100  [0603]
R?#37  1  [0603]
S?  SW-DPST  [DPST-4]
U?#8  EFM32GG280F1024-QFP100  [ENMR-LQFP100_N]
X?#3  48MHz  [MA-506]
Y?#2  32.768kHz  [R38]

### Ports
GG_I2C0_SCL, GG_I2C0_SDA, GG_U0_RX, GG_U0_TX, GG_U1_RX, GG_U1_TX, GG_US0_CLK, GG_US0_CS0, GG_US0_RX, GG_US0_TX, GG_US1_CLK, GG_US1_CS, GG_US1_RX, GG_US1_TX, GG_US2_CLK, GG_US2_CS, GG_US2_RX, GG_US2_TX, INT_BMP388, INT_BNO055, INT_FireFlyX1, nRST_FireFlyX1, RST_SX1276, TIM0_CC0, TIM0_CC1, TIM0_CC2, TIM1_CC0, TIM1_CC1, TIM1_CC2

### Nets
3.3V: C?#58.1 C?#59.1 C?#60.1 C?#61.1 C?#62.1 C?#63.1 C?#64.1 J?#2.1 J?#3.4(Vdd) L?#4.1 R?#31.2 R?#32.2 R?#33.2 R?#34.2 R?#35.2 U?#8.8(IOVDD_0) U?#8.17(IOVDD_1) U?#8.31(IOVDD_2) U?#8.44(IOVDD_3) U?#8.57(VDD_DREG) U?#8.82(IOVDD_5)
GND: C?#54.2 C?#55.2 C?#56.2 C?#57.2 C?#58.2 C?#59.2 C?#60.2 C?#61.2 C?#62.2 C?#63.2 C?#64.2 C?#65.2 C?#66.2 C?#67.2 C?#68.2 J?#2.3 J?#2.5 J?#2.15 J?#2.17 J?#2.19 J?#3.6(Vss) R?#36.1 U?#8.16(VSS) U?#8.32(VSS) U?#8.58(VSS) U?#8.83(VSS)
DBG_nRESET: C?#65.1 J?#2.10 S?.2(NO1) U?#8.36(RESETn)
DBG_SWCLK: J?#2.4 U?#8.76(PF0)
DBG_SWDIO: J?#2.2 U?#8.77(PF1)
DBG_SWO: J?#2.6 U?#8.78(PF2)
GG_US0_CLK: J?#3.5(CLK) U?#8.94(PE10) ; port GG_US0_CLK
GG_US0_CS1: J?#3.2(CD/DAT3) R?#34.1 U?#8.98(PE14)
GG_US0_RX: J?#3.7(DAT0) U?#8.95(PE11) ; port GG_US0_RX
GG_US0_TX: J?#3.3(CMD) U?#8.96(PE12) ; port GG_US0_TX
HF_XTAL0: C?#54.1 U?#8.42(PB13) X?#3.1
HF_XTAL1: C?#55.1 U?#8.43(PB14) X?#3.4
LF_XTAL0: C?#56.1 U?#8.24(PB7) Y?#2.1(OSC1)
LF_XTAL1: C?#57.1 U?#8.25(PB8) Y?#2.2(OSC2)
TDI: J?#2.8
TRACECLK: J?#2.12 U?#8.53(PD7)
TRACED0: J?#2.14 U?#8.52(PD6)
TRACED1: J?#2.16 U?#8.4(PA3)
TRACED2: J?#2.18 U?#8.50(PD4)
TRACED3: J?#2.20 U?#8.51(PD5)
NetB?_10: R?#31.1 U?#8.1(PA0) ; port GG_I2C0_SDA
NetB?_11: R?#32.1 U?#8.2(PA1) ; port GG_I2C0_SCL
NetB?_13: U?#8.26(PA7) ; port INT_FireFlyX1
NetB?_19: U?#8.27(PA8) ; port nRST_FireFlyX1
NetC?#66_1: C?#66.1 U?#8.59(DECOUPLE)
NetC?#67_1: C?#67.1 C?#68.1 R?#37.2 U?#8.41(AVDD_1) U?#8.45(AVDD_0)
NetIC?#3_2: U?#8.97(PE13) ; port GG_US0_CS0
NetIC?#3_4: U?#8.28(PA9) ; port RST_SX1276
NetJ?#3_1: J?#3.1(DAT2) R?#35.1
NetJ?#3_8: J?#3.8(DAT1) R?#33.1
NetL?#4_2: L?#4.2 R?#37.1
NetR?#28_2: U?#8.72(PC12) ; port GG_U1_TX
NetR?#29_2: U?#8.73(PC13) ; port GG_U1_RX
NetR?#36_2: R?#36.2 S?.1(COMMON1)
NetU?#2_2: U?#8.61(PE1) ; port GG_U0_TX
NetU?#2_30: U?#8.60(PE0) ; port GG_U0_RX
NetU?#3_7: U?#8.6(PA5) ; port INT_BMP388
NetU?#4_14: U?#8.7(PA6) ; port INT_BNO055
NetU?#5_1: U?#8.18(PC0) ; port GG_US1_TX
NetU?#5_14: U?#8.49(PD3) ; port GG_US1_CS
NetU?#5_16: U?#8.48(PD2) ; port GG_US1_CLK
NetU?#8_9: U?#8.9(PB0) ; port TIM1_CC0
NetU?#8_10: U?#8.10(PB1) ; port TIM1_CC1
NetU?#8_11: U?#8.11(PB2) ; port TIM1_CC2
NetU?#8_19: U?#8.19(PC1) ; port GG_US1_RX
NetU?#8_20: U?#8.20(PC2) ; port GG_US2_TX
NetU?#8_21: U?#8.21(PC3) ; port GG_US2_RX
NetU?#8_22: U?#8.22(PC4) ; port GG_US2_CLK
NetU?#8_23: U?#8.23(PC5) ; port GG_US2_CS
NetU?#8_84: U?#8.84(PF6) ; port TIM0_CC0
NetU?#8_85: U?#8.85(PF7) ; port TIM0_CC1
NetU?#8_86: U?#8.86(PF8) ; port TIM0_CC2

Not connected (* = marked no-connect by the designer): J?#2 7 9 11 13; J?#3 9(Card_Detect) 10(Card_Detect); S? 3(COMMON2) 4(NO2); U?#8 3(PA2) 5(PA4) 12(PB3) 13(PB4) 14(PB5) 15(PB6) 29(PA10) 30(PA11) 33(PA12) 34(PA13) 35(PA14) 37(PB9) 38(PB10) 39(PB11) 40(PB12) 46(PD0) 47(PD1) 54(PD8) 55(PC6) 56(PC7) 62(PE2) 63(PE3) 64(PE4) 65(PE5) 66(PE6) 67(PE7) 68(PC8) 69(PC9) 70(PC10) 71(PC11) 74(PC14) 75(PC15) 79(PF3) 80(PF4) 81(PF5) 87(PF9) 88(PD9) 89(PD10) 90(PD11) 91(PD12) 92(PE8) 93(PE9) 99(PE15) 100(PA15)

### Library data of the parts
C?#54-C?#68 = Capacitor
J?#2 = 62102021021: Pin Header WR-PHD, pitch 1.27 mm, SMD, Vertical, dual row, 20 pin; Rated Current: 1 A; Pin Number: 20; Pitch: 1.27 mm; Working Voltage: 100 VAC; Contact Resistance: 20 mOhm; Insulation Resistance: >1000 MOhm
J?#3 = 693071010811: WR-CRD Micro SD Card Connector, Push & Push, with card detection; Rated Current: 0.5A; Working Voltage: 500V AC
L?#4 = Inductor
R?#31-R?#37 = Resistor
S? = SW-DPST: Double-Pole, Single-Throw Switch
U?#8 = EFM32GG280F1024-QFP100: EFM32 Giant Gecko, M3 ARM Cortex CPU, 1024 KB Flash, 128 KB RAM, 1.85 - 3.8 V Supply, 48 MHz Max Speed, -40 to 85 degC, 100-Pin LQFP, RoHS Compliant; Flash (KB): 1024; GPIO: 86; LESENSE: Y; Max Speed (MHz): 48; OPAMPS: 3; RAM (KB): 128
X?#3 = Crystal 1-4: Crystal (Pins 1 and 4)
Y?#2 = XTAL: Crystal Oscillator

## Sheet ASBB_Servo.SchDoc
size A4
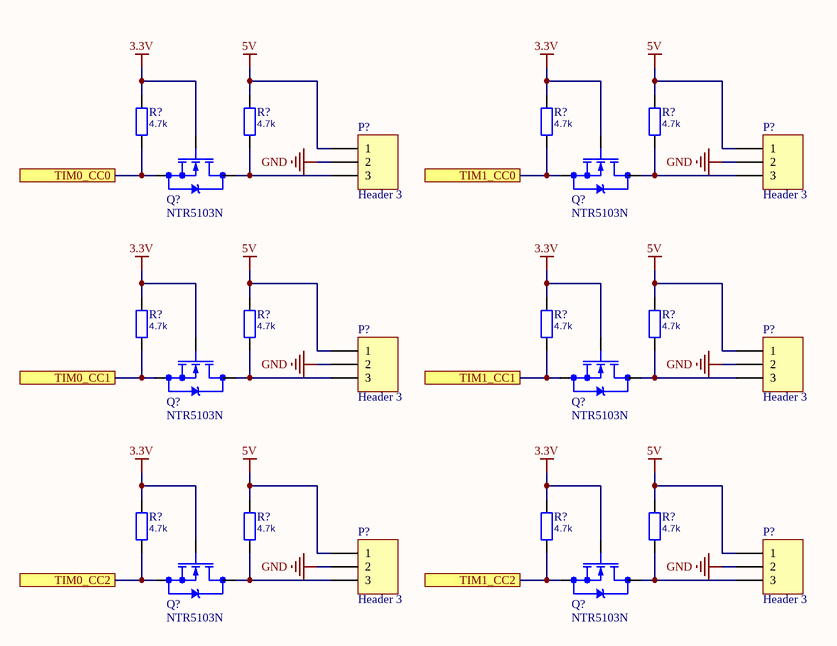
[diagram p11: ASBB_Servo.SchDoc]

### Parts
(Parts that share a designator on the sheet are numbered #1, #2 ... from top to bottom, then left to right.)
P?#2  Header 3  [HDR1X3]
P?#3  Header 3  [HDR1X3]
P?#4  Header 3  [HDR1X3]
P?#5  Header 3  [HDR1X3]
P?#6  Header 3  [HDR1X3]
P?#7  Header 3  [HDR1X3]
Q?#5  NTR5103N  [SOT23]
Q?#6  NTR5103N  [SOT23]
Q?#7  NTR5103N  [SOT23]
Q?#8  NTR5103N  [SOT23]
Q?#9  NTR5103N  [SOT23]
Q?#10  NTR5103N  [SOT23]
R?#38  4.7k  [0603]
R?#39  4.7k  [0603]
R?#40  4.7k  [0603]
R?#41  4.7k  [0603]
R?#42  4.7k  [0603]
R?#43  4.7k  [0603]
R?#44  4.7k  [0603]
R?#45  4.7k  [0603]
R?#46  4.7k  [0603]
R?#47  4.7k  [0603]
R?#48  4.7k  [0603]
R?#49  4.7k  [0603]

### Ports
TIM0_CC0, TIM0_CC1, TIM0_CC2, TIM1_CC0, TIM1_CC1, TIM1_CC2

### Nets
3.3V: Q?#5.1(G) Q?#6.1(G) Q?#7.1(G) Q?#8.1(G) Q?#9.1(G) Q?#10.1(G) R?#38.2 R?#40.2 R?#42.2 R?#44.2 R?#46.2 R?#48.2
5V: P?#2.1 P?#3.1 P?#4.1 P?#5.1 P?#6.1 P?#7.1 R?#39.2 R?#41.2 R?#43.2 R?#45.2 R?#47.2 R?#49.2
GND: P?#2.2 P?#3.2 P?#4.2 P?#5.2 P?#6.2 P?#7.2
NetIC?#4_30: Q?#10.2(S) R?#48.1 ; port TIM1_CC2
NetIC?#4_31: Q?#8.2(S) R?#44.1 ; port TIM1_CC1
NetIC?#4_45: Q?#5.2(S) R?#38.1 ; port TIM0_CC0
NetIC?#4_47: Q?#7.2(S) R?#42.1 ; port TIM0_CC1
NetIC?#4_49: Q?#9.2(S) R?#46.1 ; port TIM0_CC2
NetIC?#4_51: Q?#6.2(S) R?#40.1 ; port TIM1_CC0
NetP?#2_3: P?#2.3 Q?#5.3(D) R?#39.1
NetP?#3_3: P?#3.3 Q?#6.3(D) R?#41.1
NetP?#4_3: P?#4.3 Q?#7.3(D) R?#43.1
NetP?#5_3: P?#5.3 Q?#8.3(D) R?#45.1
NetP?#6_3: P?#6.3 Q?#9.3(D) R?#47.1
NetP?#7_3: P?#7.3 Q?#10.3(D) R?#49.1

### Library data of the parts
P?#2-P?#7 = Header 3: Header, 3-Pin
Q?#5-Q?#10 = NMOS SOT23: N-Channel MOSFET SOT23
R?#38-R?#49 = Resistor

## Sheet ASBB_MightyGecko.SchDoc
size A4
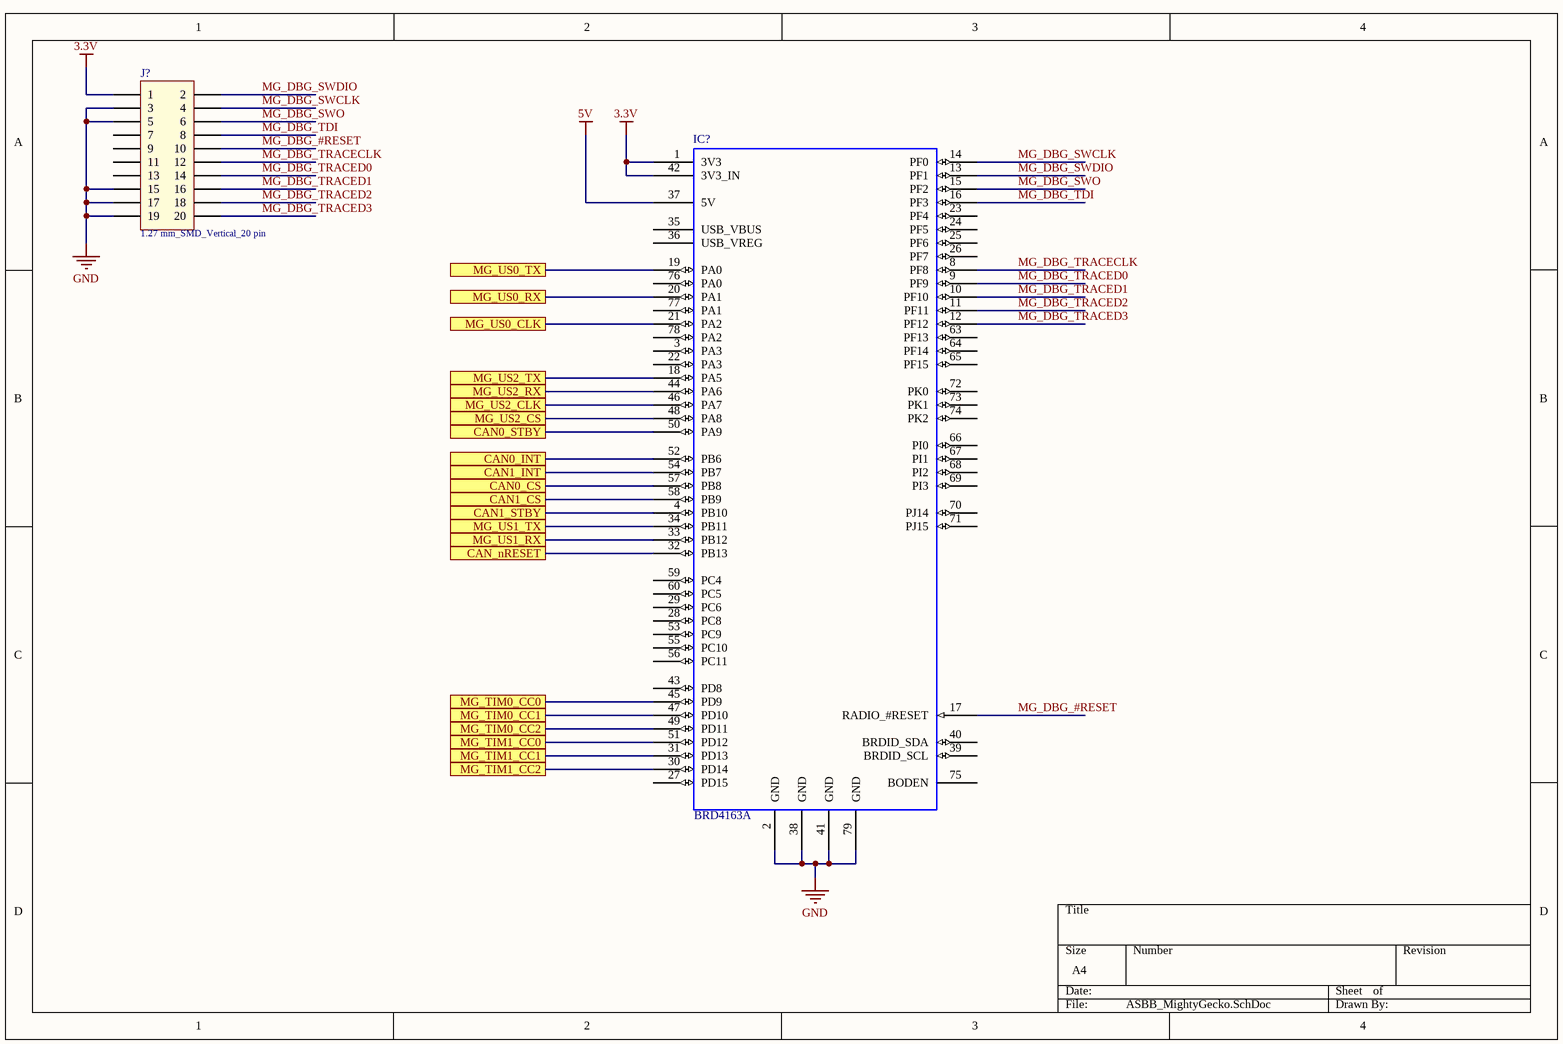
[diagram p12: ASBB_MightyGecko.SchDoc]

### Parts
(Parts that share a designator on the sheet are numbered #1, #2 ... from top to bottom, then left to right.)
IC?#4  BRD4163A  [80-Pin SiLabs Module]
J?#4  1.27 mm_SMD_Vertical_20 pin  [62102021021]

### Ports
CAN0_CS, CAN0_INT, CAN0_STBY, CAN1_CS, CAN1_INT, CAN1_STBY, CAN_nRESET, MG_TIM0_CC0, MG_TIM0_CC1, MG_TIM0_CC2, MG_TIM1_CC0, MG_TIM1_CC1, MG_TIM1_CC2, MG_US0_CLK, MG_US0_RX, MG_US0_TX, MG_US1_RX, MG_US1_TX, MG_US2_CLK, MG_US2_CS, MG_US2_RX, MG_US2_TX

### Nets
3.3V: IC?#4.1(3V3) IC?#4.42(3V3_IN) J?#4.1
5V: IC?#4.37(5V)
GND: IC?#4.2(GND) IC?#4.38(GND) IC?#4.41(GND) IC?#4.79(GND) J?#4.3 J?#4.5 J?#4.15 J?#4.17 J?#4.19
MG_DBG_#RESET: IC?#4.17(RADIO_#RESET) J?#4.10
MG_DBG_SWCLK: IC?#4.14(PF0) J?#4.4
MG_DBG_SWDIO: IC?#4.13(PF1) J?#4.2
MG_DBG_SWO: IC?#4.15(PF2) J?#4.6
MG_DBG_TDI: IC?#4.16(PF3) J?#4.8
MG_DBG_TRACECLK: IC?#4.8(PF8) J?#4.12
MG_DBG_TRACED0: IC?#4.9(PF9) J?#4.14
MG_DBG_TRACED1: IC?#4.10(PF10) J?#4.16
MG_DBG_TRACED2: IC?#4.11(PF11) J?#4.18
MG_DBG_TRACED3: IC?#4.12(PF12) J?#4.20
NetIC?#4_4: IC?#4.4(PB10) ; port CAN1_STBY
NetIC?#4_18: IC?#4.18(PA5) ; port MG_US2_TX
NetIC?#4_19: IC?#4.19(PA0) ; port MG_US0_TX
NetIC?#4_20: IC?#4.20(PA1) ; port MG_US0_RX
NetIC?#4_21: IC?#4.21(PA2) ; port MG_US0_CLK
NetIC?#4_30: IC?#4.30(PD14) ; port MG_TIM1_CC2
NetIC?#4_31: IC?#4.31(PD13) ; port MG_TIM1_CC1
NetIC?#4_32: IC?#4.32(PB13) ; port CAN_nRESET
NetIC?#4_33: IC?#4.33(PB12) ; port MG_US1_RX
NetIC?#4_34: IC?#4.34(PB11) ; port MG_US1_TX
NetIC?#4_44: IC?#4.44(PA6) ; port MG_US2_RX
NetIC?#4_45: IC?#4.45(PD9) ; port MG_TIM0_CC0
NetIC?#4_46: IC?#4.46(PA7) ; port MG_US2_CLK
NetIC?#4_47: IC?#4.47(PD10) ; port MG_TIM0_CC1
NetIC?#4_48: IC?#4.48(PA8) ; port MG_US2_CS
NetIC?#4_49: IC?#4.49(PD11) ; port MG_TIM0_CC2
NetIC?#4_50: IC?#4.50(PA9) ; port CAN0_STBY
NetIC?#4_51: IC?#4.51(PD12) ; port MG_TIM1_CC0
NetIC?#4_52: IC?#4.52(PB6) ; port CAN0_INT
NetIC?#4_54: IC?#4.54(PB7) ; port CAN1_INT
NetIC?#4_57: IC?#4.57(PB8) ; port CAN0_CS
NetIC?#4_58: IC?#4.58(PB9) ; port CAN1_CS

Not connected (* = marked no-connect by the designer): IC?#4 3(PA3) 5(NC) 6(NC) 7(NC) 22(PA3) 23(PF4) 24(PF5) 25(PF6) 26(PF7) 27(PD15) 28(PC8) 29(PC6) 35(USB_VBUS) 36(USB_VREG) 39(BRDID_SCL) 40(BRDID_SDA) 43(PD8) 53(PC9) 55(PC10) 56(PC11) 59(PC4) 60(PC5) 61(NC) 62(NC) 63(PF13) 64(PF14) 65(PF15) 66(PI0) 67(PI1) 68(PI2) 69(PI3) 70(PJ14) 71(PJ15) 72(PK0) 73(PK1) 74(PK2) 75(BODEN) 76(PA0) 77(PA1) 78(PA2) 80(NC); J?#4 7 9 11 13

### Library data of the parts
IC?#4 = SLWRB4163A
J?#4 = 62102021021: as J?#2 on sheet ASBB_GiantGecko

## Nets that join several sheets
3.3V: ASBB_5VBuck (?.VOUT C?#21.1 C?#22.1 C?#25.2), ASBB_USBUART (5 pins), ASBB_BMP388 (5 pins), ASBB_BNO055 (5 pins), ASBB_MCP25625 (8 pins), ASBB_FireflyX1 (L?#3.1), ASBB_SX1278 (IC?#3.8 IC?#3.13), ASBB_GiantGecko (21 pins), ASBB_Servo (12 pins), ASBB_MightyGecko (IC?#4.1 IC?#4.42 J?#4.1)
5V: ASBB_5VBuck (8 pins), ASBB_MAX98357 (7 pins), ASBB_MCP25625 (C?#42.1 C?#50.2 U?#6.27 U?#7.27), ASBB_Servo (12 pins), ASBB_MightyGecko (IC?#4.37)
GND: ASBB_VarBuck (11 pins), ASBB_5VBuck (17 pins), ASBB_USBUART (13 pins), ASBB_BMP388 (6 pins), ASBB_BNO055 (13 pins), ASBB_MAX98357 (10 pins), ASBB_MCP25625 (14 pins), ASBB_FireflyX1 (8 pins), ASBB_SX1278 (IC?#3.1), ASBB_GiantGecko (26 pins), ASBB_Servo (6 pins), ASBB_MightyGecko (9 pins)
GG_US0_CLK: ASBB_SX1278 (IC?#3.12), ASBB_GiantGecko (J?#3.5 U?#8.94)
GG_US0_RX: ASBB_SX1278 (IC?#3.11), ASBB_GiantGecko (J?#3.7 U?#8.95)
GG_US0_TX: ASBB_SX1278 (IC?#3.10), ASBB_GiantGecko (J?#3.3 U?#8.96)
NetB?_10: ASBB_BMP388 (U?#3.4), ASBB_BNO055 (U?#4.20), ASBB_FireflyX1 (B?.10), ASBB_GiantGecko (R?#31.1 U?#8.1)
NetB?_11: ASBB_BMP388 (U?#3.2), ASBB_BNO055 (U?#4.19), ASBB_FireflyX1 (B?.11), ASBB_GiantGecko (R?#32.1 U?#8.2)
NetB?_13: ASBB_FireflyX1 (B?.13), ASBB_GiantGecko (U?#8.26)
NetB?_19: ASBB_FireflyX1 (B?.19 R?#30.1), ASBB_GiantGecko (U?#8.27)
NetIC?#3_2: ASBB_SX1278 (IC?#3.2), ASBB_GiantGecko (U?#8.97)
NetIC?#3_4: ASBB_SX1278 (IC?#3.4), ASBB_GiantGecko (U?#8.28)
NetIC?#4_4: ASBB_MCP25625 (U?#7.5), ASBB_MightyGecko (IC?#4.4)
NetIC?#4_19: ASBB_MCP25625 (U?#6.15 U?#7.15), ASBB_MightyGecko (IC?#4.19)
NetIC?#4_20: ASBB_MCP25625 (U?#6.16 U?#7.16), ASBB_MightyGecko (IC?#4.20)
NetIC?#4_21: ASBB_MCP25625 (U?#6.14 U?#7.14), ASBB_MightyGecko (IC?#4.21)
NetIC?#4_30: ASBB_Servo (Q?#10.2 R?#48.1), ASBB_MightyGecko (IC?#4.30)
NetIC?#4_31: ASBB_Servo (Q?#8.2 R?#44.1), ASBB_MightyGecko (IC?#4.31)
NetIC?#4_32: ASBB_MCP25625 (U?#6.18 U?#7.18), ASBB_MightyGecko (IC?#4.32)
NetIC?#4_33: ASBB_USBUART (U?#2.6), ASBB_MightyGecko (IC?#4.33)
NetIC?#4_34: ASBB_USBUART (U?#2.5), ASBB_MightyGecko (IC?#4.34)
NetIC?#4_45: ASBB_Servo (Q?#5.2 R?#38.1), ASBB_MightyGecko (IC?#4.45)
NetIC?#4_47: ASBB_Servo (Q?#7.2 R?#42.1), ASBB_MightyGecko (IC?#4.47)
NetIC?#4_49: ASBB_Servo (Q?#9.2 R?#46.1), ASBB_MightyGecko (IC?#4.49)
NetIC?#4_50: ASBB_MCP25625 (U?#6.5), ASBB_MightyGecko (IC?#4.50)
NetIC?#4_51: ASBB_Servo (Q?#6.2 R?#40.1), ASBB_MightyGecko (IC?#4.51)
NetIC?#4_52: ASBB_MCP25625 (U?#6.13), ASBB_MightyGecko (IC?#4.52)
NetIC?#4_54: ASBB_MCP25625 (U?#7.13), ASBB_MightyGecko (IC?#4.54)
NetIC?#4_57: ASBB_MCP25625 (U?#6.17), ASBB_MightyGecko (IC?#4.57)
NetIC?#4_58: ASBB_MCP25625 (U?#7.17), ASBB_MightyGecko (IC?#4.58)
NetR?#28_2: ASBB_FireflyX1 (R?#28.2), ASBB_GiantGecko (U?#8.72)
NetR?#29_2: ASBB_FireflyX1 (R?#29.2), ASBB_GiantGecko (U?#8.73)
NetU?#2_2: ASBB_USBUART (U?#2.2), ASBB_GiantGecko (U?#8.61)
NetU?#2_30: ASBB_USBUART (U?#2.30), ASBB_GiantGecko (U?#8.60)
NetU?#3_7: ASBB_BMP388 (U?#3.7), ASBB_GiantGecko (U?#8.6)
NetU?#4_14: ASBB_BNO055 (U?#4.14), ASBB_GiantGecko (U?#8.7)
NetU?#5_1: ASBB_MAX98357 (U?#5.1), ASBB_GiantGecko (U?#8.18)
NetU?#5_14: ASBB_MAX98357 (U?#5.14), ASBB_GiantGecko (U?#8.49)
NetU?#5_16: ASBB_MAX98357 (U?#5.16), ASBB_GiantGecko (U?#8.48)
V_IN: ASBB_VarBuck (5 pins), ASBB_5VBuck (5 pins)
